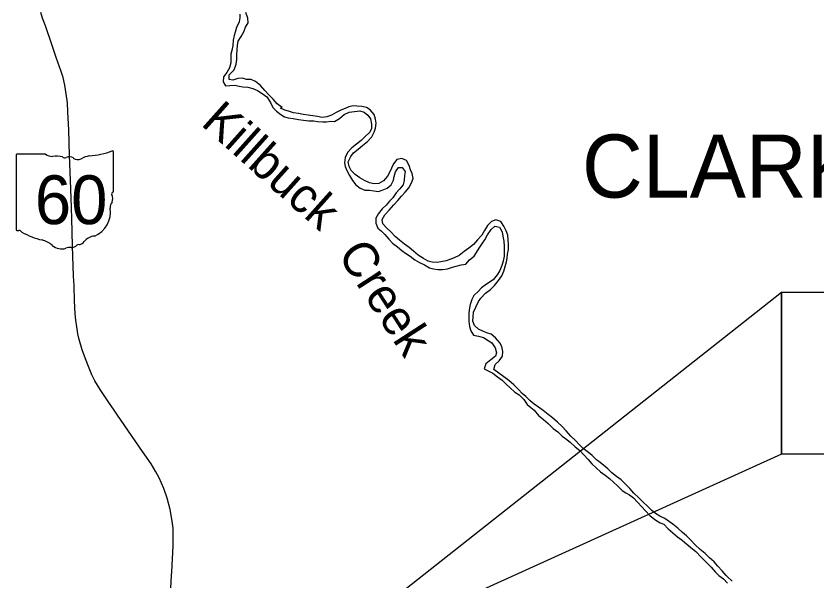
# Model space of a CAD drawing. Extents: x -6.3 to 34, y 0 to 22.
# Drawn here: x 2.568 to 4.052, y 18.433 to 19.479 of the extents above; entities that cross this region are included whole.
import ezdxf

# ---------------------------------------------------------------- set-up
doc = ezdxf.new("R2010")
doc.units = 0
for name, color, linetype in [('BR_P_Gen_Text', 7, 'Continuous'), ('GM_X_Major_River', 7, 'Continuous'), ('GM_X_Major_River_Text', 7, 'Continuous'), ('GM_X_State_Route', 7, 'Continuous'), ('GM_X_State_Shield', 7, 'Continuous'), ('GM_X_Township_Text', 7, 'Continuous')]:
    doc.layers.add(name, color=color, linetype=linetype)

msp = doc.modelspace()

# ---------------------------------------------------------------- linework, layer by layer
at = {"layer": 'BR_P_Gen_Text'}
for points in [[(3.9868, 18.9676), (3.9868, 18.6674), (3.0917, 18.2621)], [(3.9868, 18.9676), (5.3955, 18.9676), (5.3955, 18.6674), (3.9868, 18.6674)]]:
    msp.add_lwpolyline(points, close=True, dxfattribs=at)
at = {"layer": 'GM_X_Major_River'}
for points in [[(2.9825, 19.4824), (2.9828, 19.4757), (2.9813, 19.4679), (2.9764, 19.4577), (2.9738, 19.4491), (2.9721, 19.4426), (2.97, 19.4343), (2.9693, 19.4242), (2.9678, 19.4149), (2.966, 19.4081), (2.9661, 19.399), (2.9659, 19.3923), (2.9636, 19.3832), (2.9582, 19.3743), (2.9523, 19.366), (2.9515, 19.3572), (2.9557, 19.3497), (2.9643, 19.3502), (2.9731, 19.3508), (2.9816, 19.349), (2.9884, 19.348), (2.9972, 19.347), (3.0065, 19.3445), (3.0151, 19.3412), (3.0239, 19.3355), (3.0325, 19.3291), (3.0393, 19.319), (3.0438, 19.3094), (3.0508, 19.3024), (3.0586, 19.2962), (3.0651, 19.2924), (3.0721, 19.2906), (3.0814, 19.2888), (3.0913, 19.2871), (3.1004, 19.2863), (3.1105, 19.2848), (3.1198, 19.2849), (3.1268, 19.2834), (3.1364, 19.2827), (3.1431, 19.2832), (3.1512, 19.284), (3.1582, 19.2838), (3.1672, 19.2893), (3.176, 19.2966), (3.185, 19.3006), (3.1951, 19.3022), (3.2047, 19.303), (3.213, 19.3007), (3.2195, 19.2953), (3.2247, 19.2883), (3.2266, 19.2787), (3.2266, 19.2702), (3.223, 19.2634), (3.2145, 19.2553), (3.2073, 19.2483), (3.1985, 19.2415), (3.1903, 19.2349), (3.182, 19.2261), (3.1779, 19.2167), (3.1767, 19.2071), (3.178, 19.2004), (3.1817, 19.1918), (3.1856, 19.1838), (3.1911, 19.1745)], [(3.0611, 19.3092), (3.0518, 19.3162), (3.0442, 19.3247), (3.0364, 19.3332), (3.0286, 19.3412), (3.021, 19.35), (3.0116, 19.3575), (3.0038, 19.3613), (2.995, 19.3615), (2.9872, 19.3636), (2.9787, 19.3633), (2.9696, 19.3601), (2.9629, 19.3611), (2.9629, 19.3702), (2.9721, 19.3793), (2.9757, 19.3895), (2.9767, 19.3986), (2.9772, 19.4076), (2.9774, 19.4165), (2.9781, 19.4245), (2.9796, 19.432), (2.9853, 19.4412), (2.9897, 19.4495), (2.993, 19.4581), (2.9979, 19.4661), (2.9976, 19.4747), (2.9939, 19.4853)], [(3.4721, 19.0063), (3.4746, 19.0151), (3.4767, 19.0237), (3.4779, 19.0302), (3.4787, 19.0377), (3.4802, 19.0463), (3.4804, 19.0549), (3.4801, 19.065), (3.479, 19.0733), (3.4759, 19.0813), (3.4719, 19.0896), (3.4662, 19.0981), (3.4571, 19.1012), (3.4488, 19.0983), (3.4413, 19.0912), (3.436, 19.0819), (3.4311, 19.0733), (3.4233, 19.0642), (3.4156, 19.0556), (3.4071, 19.0488), (3.3983, 19.043), (3.3888, 19.0352), (3.38, 19.0312), (3.372, 19.0281), (3.365, 19.0257), (3.3549, 19.0236), (3.3482, 19.0225), (3.3391, 19.023), (3.3316, 19.025), (3.3227, 19.0301), (3.3131, 19.0361), (3.3045, 19.0433), (3.2967, 19.0502), (3.2876, 19.0567), (3.2785, 19.0636), (3.2702, 19.0706), (3.2626, 19.0791), (3.2553, 19.0861), (3.2473, 19.0938), (3.2462, 19.1019), (3.2511, 19.1107), (3.2593, 19.1193), (3.2681, 19.1292), (3.2755, 19.1371), (3.2822, 19.1451), (3.2892, 19.1527), (3.2959, 19.161), (3.3008, 19.1701), (3.3041, 19.1779), (3.3022, 19.1873), (3.2991, 19.194), (3.2964, 19.202), (3.2912, 19.2111), (3.2826, 19.2152), (3.2738, 19.2133), (3.2674, 19.2053), (3.2636, 19.1969), (3.2607, 19.1902), (3.2561, 19.1821), (3.2487, 19.1738), (3.2399, 19.169), (3.2313, 19.1682), (3.2228, 19.17), (3.2139, 19.1741), (3.2051, 19.1792), (3.1965, 19.1851), (3.189, 19.1929), (3.185, 19.2004), (3.1832, 19.209), (3.1883, 19.2188), (3.1932, 19.2254), (3.202, 19.2321), (3.2102, 19.2392), (3.219, 19.2465), (3.2272, 19.2554), (3.2316, 19.264), (3.2341, 19.2712), (3.2354, 19.2806), (3.2343, 19.2876), (3.2314, 19.2964), (3.2241, 19.3054), (3.2176, 19.3093), (3.2085, 19.3111), (3.1995, 19.3121), (3.1927, 19.3125), (3.1847, 19.3107), (3.1775, 19.3073), (3.1697, 19.3044), (3.1612, 19.3004), (3.1527, 19.2955), (3.1441, 19.292), (3.1353, 19.2912), (3.1265, 19.293), (3.1089, 19.2955), (3.1001, 19.2965), (3.0912, 19.2982), (3.0819, 19.2997), (3.0728, 19.3025), (3.0661, 19.3046), (3.058, 19.3082), (3.0611, 19.3092)], [(3.1911, 19.1745), (3.1976, 19.1665), (3.2055, 19.1598), (3.2143, 19.1564), (3.2226, 19.1562), (3.2309, 19.1552), (3.2394, 19.1542), (3.2464, 19.1561), (3.2555, 19.16), (3.2629, 19.1663), (3.2673, 19.1752), (3.2683, 19.1819), (3.2711, 19.1902), (3.2765, 19.1983), (3.2835, 19.1983), (3.2887, 19.1911), (3.288, 19.1833), (3.287, 19.175), (3.285, 19.1662), (3.2783, 19.1581), (3.2723, 19.1513), (3.2662, 19.1425), (3.26, 19.1359), (3.2538, 19.1284), (3.2463, 19.1218), (3.2396, 19.113), (3.2345, 19.1044), (3.2346, 19.0951), (3.2382, 19.086), (3.2447, 19.0814), (3.251, 19.0744), (3.2588, 19.0656), (3.2656, 19.0581), (3.2747, 19.0512), (3.2828, 19.0445), (3.2893, 19.0398), (3.2984, 19.0342), (3.3069, 19.0277), (3.3158, 19.0223), (3.3246, 19.018), (3.334, 19.0126), (3.3415, 19.0105), (3.3498, 19.0098), (3.3581, 19.0098), (3.3674, 19.0107), (3.3765, 19.0136), (3.3837, 19.0159), (3.3925, 19.0181), (3.4013, 19.0191), (3.4085, 19.0277), (3.417, 19.0343), (3.4211, 19.0408), (3.426, 19.0491), (3.4322, 19.058), (3.4368, 19.0645), (3.4414, 19.0739), (3.4484, 19.0835), (3.4553, 19.09), (3.4639, 19.088), (3.4686, 19.0792), (3.4702, 19.0712), (3.4716, 19.0618), (3.4724, 19.0525), (3.4722, 19.0434), (3.4722, 19.0341), (3.4705, 19.0252), (3.4682, 19.0167), (3.4646, 19.0075), (3.4594, 18.9995), (3.4522, 18.9901), (3.4455, 18.9862), (3.4373, 18.9807), (3.4303, 18.9755), (3.4241, 18.9689), (3.4164, 18.9614), (3.4125, 18.9541), (3.4095, 18.945), (3.4082, 18.9385), (3.407, 18.9294), (3.4067, 18.9221), (3.407, 18.9138), (3.4081, 18.9042), (3.411, 18.8957), (3.4155, 18.8877), (3.4248, 18.8862), (3.4339, 18.8834), (3.443, 18.8782), (3.4495, 18.8736), (3.4557, 18.8645), (3.4581, 18.8555), (3.4563, 18.849), (3.4478, 18.8424), (3.4383, 18.8346), (3.4357, 18.8255), (3.4443, 18.8211), (3.4516, 18.8173), (3.4599, 18.8109), (3.4688, 18.8044), (3.4761, 18.7972), (3.4839, 18.7902), (3.4917, 18.7827)], [(3.8841, 18.4429), (3.8764, 18.4516), (3.8688, 18.4604), (3.8618, 18.4682), (3.8532, 18.4759), (3.8451, 18.4834), (3.836, 18.4908), (3.8266, 18.4996), (3.8186, 18.5084), (3.8105, 18.5161), (3.8032, 18.5228), (3.7946, 18.5308), (3.7852, 18.5381), (3.7787, 18.5424), (3.7702, 18.5484), (3.7613, 18.553), (3.753, 18.5579), (3.7462, 18.5633), (3.7382, 18.5715), (3.7301, 18.579), (3.7218, 18.587), (3.7129, 18.5955), (3.7053, 18.6038), (3.6973, 18.6123), (3.6892, 18.6198), (3.6809, 18.6265), (3.6718, 18.6332), (3.6645, 18.6404), (3.6569, 18.6466), (3.6504, 18.652), (3.6437, 18.6574), (3.6353, 18.6652), (3.6286, 18.6709), (3.6192, 18.6781), (3.6127, 18.6845), (3.6049, 18.6928), (3.596, 18.701), (3.5874, 18.7109), (3.5798, 18.7191), (3.5715, 18.7271), (3.5621, 18.7346), (3.5543, 18.741), (3.5445, 18.7485), (3.5359, 18.7544), (3.5278, 18.7601), (3.5208, 18.7665), (3.5127, 18.7743), (3.5057, 18.7802), (3.4989, 18.7872), (3.4901, 18.796), (3.4812, 18.804), (3.4721, 18.8107), (3.4627, 18.8174), (3.4536, 18.8243), (3.4557, 18.8334), (3.4634, 18.8407), (3.4696, 18.8488), (3.4703, 18.8579), (3.4682, 18.8669), (3.4642, 18.8739), (3.4567, 18.8827), (3.4484, 18.8897), (3.4406, 18.8925), (3.4341, 18.8948), (3.425, 18.8991), (3.4174, 18.9056), (3.4143, 18.9139), (3.415, 18.9217), (3.4158, 18.9307), (3.4201, 18.9399), (3.425, 18.95), (3.4294, 18.9565), (3.4381, 18.9654), (3.4471, 18.9724), (3.4546, 18.98), (3.4618, 18.9891), (3.468, 18.9975), (3.4721, 19.0063)], [(3.4917, 18.7827), (3.4925, 18.7823), (3.5003, 18.7776), (3.5089, 18.7688), (3.5151, 18.7595), (3.5216, 18.7541), (3.5281, 18.7489), (3.5362, 18.7394), (3.5453, 18.7319), (3.5542, 18.7244), (3.563, 18.7154), (3.5719, 18.709), (3.5799, 18.701), (3.5864, 18.6963), (3.595, 18.6896), (3.6039, 18.6811), (3.6125, 18.6741), (3.6203, 18.6661), (3.6281, 18.6579), (3.6349, 18.6496), (3.643, 18.6421), (3.6513, 18.6349), (3.6596, 18.629), (3.6679, 18.6225), (3.6757, 18.6153), (3.6823, 18.6091), (3.6914, 18.6004), (3.6981, 18.5962), (3.7046, 18.5921), (3.7122, 18.5867), (3.7197, 18.5787), (3.7275, 18.5699), (3.7341, 18.5632), (3.7432, 18.5537), (3.7533, 18.5454), (3.7614, 18.5403), (3.7681, 18.5382), (3.7762, 18.5295), (3.7853, 18.522), (3.7936, 18.5148), (3.8022, 18.5086), (3.8113, 18.5008), (3.8186, 18.4949), (3.8277, 18.4872), (3.8379, 18.4766), (3.8468, 18.4676), (3.8559, 18.4583), (3.8634, 18.45), (3.8701, 18.4429)], [(3.8701, 18.4429), (3.8702, 18.4428), (3.879, 18.4368), (3.8863, 18.4288)], [(3.8949, 18.4325), (3.8855, 18.4413), (3.8841, 18.4429)]]:
    msp.add_lwpolyline(points, dxfattribs=at)
at = {"layer": 'GM_X_State_Route'}
for points in [[(2.856, 18.4429), (2.8564, 18.45), (2.8588, 18.498), (2.8592, 18.5125), (2.8587, 18.5306), (2.857, 18.5434), (2.8536, 18.5652), (2.8481, 18.5862), (2.8414, 18.6042), (2.8329, 18.6236), (2.8267, 18.6351), (2.818, 18.6495), (2.8024, 18.6727), (2.7832, 18.7006), (2.7548, 18.7414), (2.7483, 18.7511), (2.7409, 18.7617), (2.7237, 18.7871), (2.7136, 18.8035), (2.7084, 18.8146), (2.7018, 18.8298), (2.6963, 18.8438), (2.6906, 18.8606), (2.6849, 18.8799), (2.6825, 18.8905), (2.6802, 18.9036), (2.6786, 18.916), (2.6776, 18.9275), (2.6763, 18.9517), (2.6752, 18.9796), (2.6745, 18.9974), (2.6724, 19.0536), (2.6711, 19.104), (2.6706, 19.1237), (2.6693, 19.159), (2.6667, 19.2213), (2.6654, 19.2676), (2.664, 19.3016), (2.663, 19.3184), (2.6607, 19.3346), (2.6583, 19.3505), (2.6551, 19.3651), (2.6516, 19.376), (2.6424, 19.4022), (2.634, 19.4259), (2.6223, 19.4605), (2.6171, 19.4746), (2.6135, 19.4856)], [(2.8697, 18.3297), (2.8671, 18.3331), (2.8609, 18.3434), (2.8563, 18.3532), (2.8539, 18.3604), (2.8528, 18.3682), (2.8521, 18.3764), (2.8532, 18.3966), (2.856, 18.4429)]]:
    msp.add_lwpolyline(points, dxfattribs=at)
at = {"layer": 'GM_X_State_Shield'}
for p, q in [((2.7484, 19.1549), (2.7484, 19.2267)), ((2.5677, 19.2209), (2.5677, 19.0838)), ((2.6224, 19.2233), (2.5695, 19.2233)), ((2.7484, 19.155), (2.7484, 19.1549))]:
    msp.add_line(p, q, dxfattribs=at)
for centre, radius, start, end in [((2.6841, 19.4103), 0.1916, 275.8445, 288.9065), ((2.7464, 19.227), 0.00201, 351.8621, 97.738), ((2.5698, 19.2212), 0.00209, 98.1301, 188.1301), ((2.635, 19.2392), 0.0203, 231.6195, 271.1119), ((2.6418, 19.1463), 0.0729, 80.4867, 94.9883), ((2.6583, 19.2219), 0.00586, 219.7921, 297.1024), ((2.6669, 19.2061), 0.0122, 54.4667, 119.1411), ((2.6826, 19.2278), 0.0147, 233.8562, 294.8282), ((2.7085, 19.1814), 0.0386, 97.3462, 120.7689), ((2.748, 19.1497), 0.00311, 107.944, 210.337), ((2.7463, 19.1547), 0.00215, 289.6038, 7.7341), ((2.7282, 19.1406), 0.0187, 340.033, 23.6496), ((2.6948, 19.1158), 0.0479, 292.3089, 8.9858), ((2.7556, 19.1249), 0.0136, 136.8065, 186.9296), ((2.5698, 19.0835), 0.00211, 171.9584, 258.3066), ((2.5702, 19.0975), 0.0161, 267.339, 280.6039), ((2.5734, 19.0759), 0.00581, 29.7484, 93.2717), ((2.6468, 19.1991), 0.1384, 240.4129, 257.1985), ((2.6056, 19.0222), 0.0433, 47.1842, 75.836), ((2.715, 19.0453), 0.0263, 94.4031, 142.5768), ((2.6524, 19.0752), 0.0275, 230.7004, 286.2918), ((2.6683, 19.0278), 0.0226, 85.6951, 111.2099), ((2.6703, 19.0649), 0.0146, 268.777, 315.5493), ((2.6835, 19.0516), 0.00412, 65.7517, 132.6484), ((2.6818, 19.0705), 0.0155, 282.8732, 323.2771)]:
    msp.add_arc(centre, radius, start, end, dxfattribs=at)

# ---------------------------------------------------------------- texts
at = {"layer": 'GM_X_Major_River_Text'}
for s, rotation, p in [('Killbuck', 318.2161, (2.9085, 19.2781)), ('Creek', 302.912, (3.1624, 19.0378))]:
    msp.add_text(s, height=0.06491, rotation=rotation, dxfattribs=at).set_placement(p)
at = {"layer": 'GM_X_State_Shield'}
msp.add_text('60', height=0.09035, dxfattribs=at).set_placement((2.6027, 19.0935))
at = {"layer": 'GM_X_Township_Text'}
msp.add_text('CLARK', height=0.11682, rotation=0, dxfattribs=at).set_placement((3.6166, 19.1426))

doc.saveas('drawing.dxf')
